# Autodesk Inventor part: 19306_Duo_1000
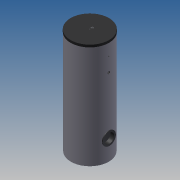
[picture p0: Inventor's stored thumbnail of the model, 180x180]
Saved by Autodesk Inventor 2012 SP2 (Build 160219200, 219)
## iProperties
allow_slope_adjustment: 0 ul
connection_type: 13 ul
flow_configuration2: 1 ul
flow_direction: 2 ul
loss_method: 0 ul
radius: 19,625 mm
description: 0:0:19306_Duo_1000
manufacturer: 0:0:Flamco Group
model: 0:0:Duo 1000
url: 0:0:www.flamcogroup.com
radius: 22,625 mm
Created: 2014-05
Part Number: 19306_Duo_1000
Material: Default
Document SubType Name: Modeling
Designer: michel
Density: 1 g/cm^3
radius: 9,500 mm
radius: 18,295 mm
radius: 12,250 mm
Author: michel
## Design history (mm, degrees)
sketch "Sketch1"
  geometry: C1 r 400 at (0, 0); 1 further point
  constraints: 1 centre point, 1 coincident
  dimensions: "d0" = 800 diameter of C1
extrude "Extrusion1" new body sketch "Sketch1" distance "d1" = 2230; taper "d2" = 0 deg
sketch "Sketch2"
  geometry: L1 (-400, 2230)-(400, 2230) reference; L2 (-400, 0)-(400, 0) reference; L3 (400, 0)-(400, 2230) reference; L4 (400, 2230)-(405, 2230); L5 (405, 2230)-(405, 2180); L6 (405, 2180)-(400, 2180); L7 (400, 2180)-(400, 2230); L8 (0, -394)-(0, 2364) reference; 1 further point
  constraints: 8 end point, 2 parallel, 1 horizontal, 1 perpendicular
  dimensions: "d3" = 5 distance of L5.end L6.end; "d4" = 50 distance of L4.end L5.end
revolve "Revolution1" sketch "Sketch2" stored, may be unused: angle "d5" = 90 deg
workplane "Work Plane1"
workplane "Work Plane2"
workplane "Work Plane3"
workplane "Work Plane4"
workplane "Work Plane5"
workplane "Work Plane6"
workplane "Work Plane11"
workplane "Work Plane12"
sketch "Sketch3"
  geometry: L1 (561.4, 2140)-(-561.4, 2140) reference; L2 (561.4, 1110)-(-561.4, 1110) reference; L3 (561.4, 960)-(-561.4, 960) reference; L4 (561.4, 330)-(-561.4, 330) reference; L5 (561.4, 70)-(-561.4, 70) reference; L6 (400, 0)-(400, 2180) reference; L7 (400, 2140)-(360, 2140); L8 (360, 2140)-(360, 2160.955); L9 (360, 2160.955)-(400, 2160.955); L10 (400, 1110)-(360, 1110); L11 (360, 1110)-(360, 1130.955); L12 (360, 1130.955)-(400, 1130.955); L13 (400, 1130.955)-(400, 1110); L14 (335, 2121.705)-(335, 2119.045); L15 (335, 2119.045)-(401, 2119.045); L16 (401, 2119.045)-(401, 2121.705); L17 (401, 2121.705)-(335, 2121.705); L18 (360, 960)-(360, 973.22); L19 (400, 960)-(360, 960); L20 (360, 973.22)-(400, 973.22); L21 (400, 973.22)-(400, 960); L22 (335, 947.75)-(335, 946.78); L23 (335, 946.78)-(401, 946.78); L24 (401, 946.78)-(401, 947.75); L25 (401, 947.75)-(335, 947.75); L26 (360, 350.955)-(400, 350.955); L27 (360, 330)-(360, 350.955); L28 (400, 330)-(360, 330); L29 (400, 350.955)-(400, 330); L30 (401, 310.375)-(335.165, 310.375); L31 (335.165, 310.375)-(335.165, 309.045); L32 (335.165, 309.045)-(401, 309.045); L33 (401, 309.045)-(401, 310.375); L34 (360, 90.955)-(400, 90.955); L35 (360, 70)-(360, 90.955); L36 (400, 70)-(360, 70); L37 (400, 90.955)-(400, 70); L38 (401, 50.375)-(335, 50.375); L39 (335, 50.375)-(335, 49.045); L40 (335, 49.045)-(401, 49.045); L41 (401, 49.045)-(401, 50.375); L42 (335, 1090.375)-(335, 1089.045); L43 (401, 1089.045)-(401, 1090.375); L44 (401, 1090.375)-(335, 1090.375); L45 (-567, 1930)-(567, 1930) reference; L46 (-567, 1630)-(567, 1630) reference; L47 (-400, 0)-(-400, 2180) reference; L48 (-400, 1930)-(-360, 1930); L49 (-360, 1930)-(-360, 1940.475); L50 (-360, 1940.475)-(-400, 1940.475); L51 (-400, 1940.475)-(-400, 1930); L52 (-401, 1919.525)-(-335, 1919.525); L53 (-335, 1919.525)-(-335, 1920.5); L54 (-335, 1920.5)-(-401, 1920.5); L55 (-401, 1920.5)-(-401, 1919.525); L56 (-400, 1630)-(-335, 1630); L57 (-335, 1630)-(-335, 1653.9); L58 (-335, 1653.9)-(-400, 1653.9); L59 (-400, 1653.9)-(-400, 1630); L60 (-401, 1606.1)-(-335, 1606.1); L61 (-335, 1606.1)-(-335, 1607.375); L62 (-335, 1607.375)-(-401, 1607.375); L63 (-401, 1607.375)-(-401, 1606.1); L64 (400, 2160.955)-(400, 2140)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; 2 further points
  constraints: 112 end point, 16 parallel, 7 horizontal, 7 perpendicular, 6 point on line, 1 collinear
  dimensions: "d19" = 40 distance of L8.end L9.end; "d21" = 40 distance of L11.end L12.end; "d70" = 20.955 distance between parallel lines of L1 L9; "d73" = 40 distance of L18.end L20.end; "d74" = 40 distance of L26.start L26.end; "d75" = 40 distance of L34.start L34.end; "d76" = 13.22 distance between parallel lines of L3 L20; "d85" = 20.955 distance between parallel lines of L2 L12; "d108" = 20.955 distance between parallel lines of L1 L15; "d109" = 2.66 distance between parallel lines of L17 L15; "d110" = 20.955 distance between parallel lines of L10 L12 (= d85); "d113" = 13.22 distance between parallel lines of L19 L20 (= d76); "d114" = 13.22 distance between parallel lines of L23 L3; "d115" = 0.97 distance between parallel lines of L25 L23; "d116" = 20.955 distance between parallel lines of L4 L26; "d117" = 20.955 distance of L26.start L27.start (= d116); "d118" = 20.955 distance between parallel lines of L32 L4; "d119" = 1.33 distance between parallel lines of L30 L32; "d120" = 20.955 distance from line of L34 L35.start (= d121); "d121" = 20.955 distance between parallel lines of L5 L34; "d122" = 20.955 distance between parallel lines of L40 L5; "d123" = 1.33 distance between parallel lines of L38 L40; "d129" = 40 distance of L50.end L49.end; "d130" = 10.475 distance of L49.end L48.end; "d131" = 10.475 distance between parallel lines of L45 L52; "d132" = 0.975 distance between parallel lines of L54 L52; "d134" = 23.9 distance between parallel lines of L46 L58; "d135" = 23.9 distance between parallel lines of L46 L60; "d136" = 1.275 distance between parallel lines of L62 L60; "d154" = 1 distance between parallel lines of L47 L55; "d155" = 1 distance between parallel lines of L47 L63; "d157" = 1 distance between parallel lines of L6 L16; "d158" = 0 distance between parallel lines of L6 L13; "d159" = 1 distance between parallel lines of L6 L43; "d160" = 0 distance between parallel lines of L6 L21; "d161" = 1 distance between parallel lines of L6 L24; "d162" = 0 distance between parallel lines of L6 L29; "d163" = 1 distance between parallel lines of L6 L33; "d164" = 0 distance between parallel lines of L6 L37; "d165" = 1 distance between parallel lines of L6 L41; "d166" = 20.955 distance between parallel lines of L65 L2 (derived); "d167" = 1.33 distance between parallel lines of L44 L65 (derived)
revolve "Revolution2" stored, may be unused: angle "d23" = 90 deg
sketch "Sketch5"
  geometry: L1 (-400, 0)-(-400, 2180) reference; L2 (-400, 0)-(-400, 435); L3 (-220, 435)-(-594, 435); L4 (-400, 435)-(-412.5, 435); L5 (-412.5, 435)-(-412.5, 575); L6 (-412.5, 575)-(-400, 575); L7 (-400, 575)-(-400, 435); L8 (-400, 0)-(400, 0) reference; 1 further point
  constraints: 12 end point, 2 parallel, 2 perpendicular, 1 horizontal, 1 point on line
  dimensions: "d35" = 435 distance of L1.start L2.end; "d36" = 12.5 distance of L5.end L6.end; "d37" = 140 distance of L4.end L5.end; "d124" = 435 distance between parallel lines of L8 L3 (= d35)
revolve "Revolution7" sketch "Sketch5" stored, may be unused: angle "d38" = 90 deg
sketch "Sketch6"
  geometry: C1 r 122.5 at (0, 0); A1 r 140 centre (0, 0) between (140, 0) and (-140, 0) reference; 1 further point
  constraints: 1 centre point, 1 coincident
  dimensions: "d39" = 245 diameter of C1
extrude "Extrusion3" join sketch "Sketch6" stored distance "d40" = 40; taper "d41" = 0 deg
sketch "Sketch7"
  geometry: C1 r 140 at (0, 0) reference; C2 r 102.5 at (0, 0); 1 further point
  constraints: 1 centre point, 1 coincident
  dimensions: "d42" = 205 diameter of C2
extrude "Extrusion4" cut sketch "Sketch7" distance "d43" = 80; taper "d44" = 0 deg
sketch "Sketch15"
  geometry: L1 (-567, 0)-(567, 0) reference; C1 r 20.955 at (0, 50); C2 r 405 at (0, 0) reference; C3 r 10.475 at (0, 0); C4 r 19.625 at (0, 50); C5 r 9.5 at (0, 0)
  constraints: 4 centre point, 3 coincident
  dimensions: "d142" = 41.91 diameter of C1; "d143" = 50 distance from line of L1 C1.centre; "d144" = 20.95 diameter of C3; "d145" = 39.25 diameter of C4; "d146" = 19 diameter of C5
revolve "Revolution9" stored, may be unused: angle "d69" = 90 deg
revolve "Revolution10" stored, may be unused: angle "d92" = 90 deg
revolve "Revolution11" stored, may be unused: angle "d93" = 90 deg
revolve "Revolution12" stored, may be unused: angle "d94" = 90 deg
revolve "Revolution13" stored, may be unused: angle "d95" = 90 deg
revolve "Revolution14" stored, may be unused: angle "d96" = 90 deg
revolve "Revolution15" stored, may be unused: angle "d97" = 90 deg
revolve "Revolution16" stored, may be unused: angle "d98" = 90 deg
revolve "Revolution17" stored, may be unused: angle "d99" = 90 deg
revolve "Revolution18" stored, may be unused: angle "d138" = 90 deg
revolve "Revolution19" stored, may be unused: angle "d139" = 90 deg
revolve "Revolution20" stored, may be unused: angle "d140" = 90 deg
revolve "Revolution21" stored, may be unused: angle "d141" = 90 deg
extrude "Extrusion11" cut sketch "Sketch15" distance "d147" = 40; taper "d148" = 0 deg
extrude "Extrusion12" join sketch "Sketch15" distance "d149" = 2; taper "d150" = 0 deg
body "Solid1"
node "Projected Loop1"
other parameters: "d12" = 0
